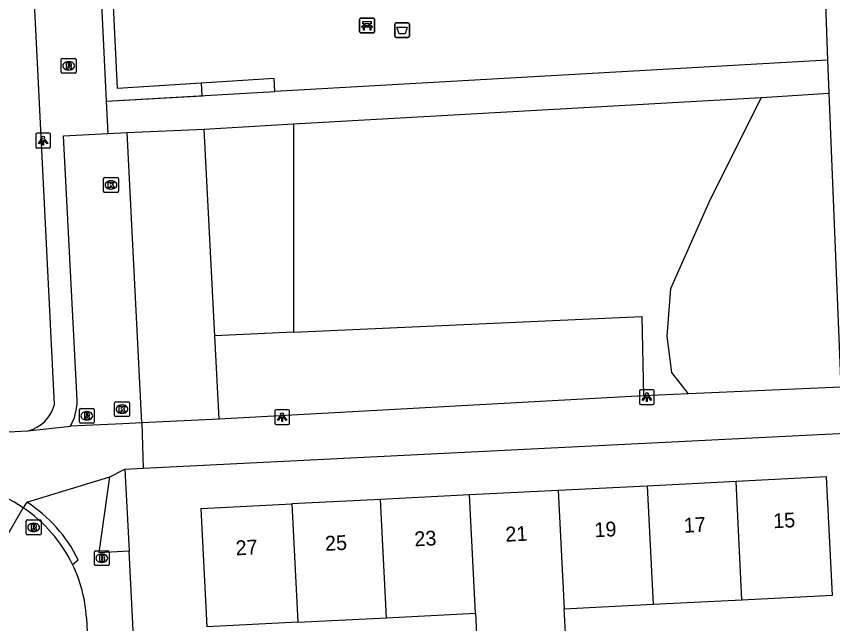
# Model space of a CAD drawing. Extents: x 161084 to 161928, y 385355 to 386522.
# Drawn here: x 161405.9 to 161461, y 386008.9 to 386049.9 of the extents above; entities that cross this region are included whole.
import ezdxf

# ---------------------------------------------------------------- set-up
doc = ezdxf.new("R2010")
doc.units = 0
for name, color, linetype in [('IMGEO_Afvalbak', 7, 'Continuous'), ('IMGEO_Bank', 7, 'Continuous'), ('IMGEO_Brandkraan', 7, 'Continuous'), ('IMGEO_Groenvoorziening', 7, 'Continuous'), ('IMGEO_Haag', 7, 'Continuous'), ('IMGEO_Kolk', 7, 'Continuous'), ('IMGEO_Lichtpunt', 7, 'Continuous'), ('IMGEO_Pand', 7, 'Continuous'), ('IMGEO_Pand_nummerreeks', 7, 'Continuous'), ('IMGEO_Parkeervlak_open', 7, 'Continuous'), ('IMGEO_Rijbaan_lokaal_open', 7, 'Continuous'), ('IMGEO_Rioolput', 7, 'Continuous'), ('IMGEO_Voetpad_halfverhard', 7, 'Continuous'), ('IMGEO_Voetpad_open', 7, 'Continuous')]:
    doc.layers.add(name, color=color, linetype=linetype)

msp = doc.modelspace()

# ---------------------------------------------------------------- linework, layer by layer
at = {"layer": 'IMGEO_Afvalbak'}
for p, q in [((161431.433, 386048.571), (161431.433, 386049.371)), ((161431.433, 386049.371), (161431.433, 386048.571)), ((161431.533, 386049.471), (161432.323, 386049.471)), ((161432.323, 386049.471), (161431.533, 386049.471)), ((161432.423, 386049.371), (161432.423, 386048.571)), ((161432.423, 386048.571), (161432.423, 386049.371)), ((161432.323, 386048.471), (161431.533, 386048.471)), ((161431.533, 386048.471), (161432.323, 386048.471))]:
    msp.add_line(p, q, dxfattribs=at)
msp.add_lwpolyline([(161431.576, 386049.185), (161432.28, 386049.185), (161432.131, 386048.715), (161431.725, 386048.715), (161431.576, 386049.185)], dxfattribs=at)
for centre, start, end in [((161431.533, 386049.371), 90, 180), ((161431.533, 386049.371), 90, 180), ((161432.323, 386049.371), 0, 90), ((161432.323, 386049.371), 360, 90), ((161431.533, 386048.571), 180, 270), ((161431.533, 386048.571), 180, 270), ((161432.323, 386048.571), 270, 0), ((161432.323, 386048.571), 270, 0)]:
    msp.add_arc(centre, 0.1, start, end, dxfattribs=at)
at = {"layer": 'IMGEO_Bank'}
for p, q in [((161429.066, 386048.86), (161429.066, 386049.701)), ((161429.066, 386049.701), (161429.066, 386048.86)), ((161429.141, 386049.785), (161429.982, 386049.785)), ((161429.982, 386049.785), (161429.141, 386049.785)), ((161429.375, 386049.291), (161429.375, 386049.397)), ((161429.419, 386049.397), (161429.419, 386049.291)), ((161429.707, 386049.403), (161429.425, 386049.403)), ((161429.425, 386049.285), (161429.707, 386049.285)), ((161429.713, 386049.291), (161429.713, 386049.397)), ((161429.757, 386049.397), (161429.757, 386049.291)), ((161430.066, 386049.71), (161430.066, 386048.869)), ((161430.066, 386048.869), (161430.066, 386049.71)), ((161429.991, 386048.785), (161429.15, 386048.785)), ((161429.15, 386048.785), (161429.991, 386048.785)), ((161429.763, 386049.183), (161429.37, 386049.183))]:
    msp.add_line(p, q, dxfattribs=at)
for points in [[(161429.313, 386049.183), (161429.171, 386049.183), (161429.283, 386049.285), (161429.369, 386049.285)], [(161429.369, 386049.403), (161429.283, 386049.403), (161429.283, 386049.564), (161429.846, 386049.564), (161429.846, 386049.403), (161429.763, 386049.403)], [(161429.763, 386049.285), (161429.846, 386049.285), (161429.958, 386049.183), (161429.819, 386049.183)], [(161429.363, 386049.176), (161429.363, 386048.969), (161429.32, 386048.969), (161429.32, 386049.176)], [(161429.813, 386049.176), (161429.813, 386048.969), (161429.769, 386048.969), (161429.769, 386049.176)]]:
    msp.add_lwpolyline(points, dxfattribs=at)
for centre, radius, start, end in [((161429.144, 386049.707), 0.0779, 92.4484, 184.2845), ((161429.144, 386049.707), 0.0779, 92.4484, 184.2845), ((161429.368, 386049.396), 0.00671, 2.8957, 87.1043), ((161429.368, 386049.292), 0.00671, 272.8957, 357.1043), ((161429.425, 386049.396), 0.00671, 92.8957, 177.1043), ((161429.425, 386049.292), 0.00671, 182.8957, 267.1043), ((161429.707, 386049.396), 0.00671, 2.8957, 87.1043), ((161429.707, 386049.292), 0.00671, 272.8957, 357.1043), ((161429.764, 386049.396), 0.00671, 92.8957, 177.1043), ((161429.764, 386049.292), 0.00671, 182.8957, 267.1043), ((161429.988, 386049.707), 0.0779, 2.4484, 94.2845), ((161429.988, 386049.707), 0.0779, 2.4484, 94.2845), ((161429.144, 386048.863), 0.0779, 182.4484, 274.2845), ((161429.144, 386048.863), 0.0779, 182.4484, 274.2845), ((161429.313, 386049.176), 0.00671, 2.8957, 87.1043), ((161429.37, 386049.176), 0.00671, 92.8957, 177.1043), ((161429.762, 386049.176), 0.00671, 2.8957, 87.1043), ((161429.819, 386049.176), 0.00671, 92.8957, 177.1043), ((161429.988, 386048.863), 0.0779, 272.4484, 4.2845), ((161429.988, 386048.863), 0.0779, 272.4484, 4.2845)]:
    msp.add_arc(centre, radius, start, end, dxfattribs=at)
at = {"layer": 'IMGEO_Brandkraan'}
for p, q in [((161411.168, 386012.895), (161411.168, 386013.747)), ((161411.243, 386013.821), (161412.095, 386013.821)), ((161411.656, 386013.601), (161411.681, 386013.601)), ((161412.169, 386013.747), (161412.169, 386012.895)), ((161411.679, 386013.041), (161411.654, 386013.041)), ((161412.095, 386012.821), (161411.243, 386012.821))]:
    msp.add_line(p, q, dxfattribs=at)
for points in [[(161411.168, 386012.895), (161411.168, 386013.747)], [(161411.243, 386013.821), (161412.095, 386013.821)], [(161411.516, 386013.521), (161411.516, 386013.121), (161411.729, 386013.121)], [(161411.747, 386013.521), (161411.516, 386013.521)], [(161412.169, 386013.747), (161412.169, 386012.895)], [(161411.695, 386013.44), (161411.641, 386013.44), (161411.641, 386013.364)], [(161411.641, 386013.364), (161411.694, 386013.364)], [(161411.703, 386013.288), (161411.641, 386013.288), (161411.641, 386013.207)], [(161411.641, 386013.207), (161411.703, 386013.207)], [(161412.095, 386012.821), (161411.243, 386012.821)]]:
    msp.add_lwpolyline(points, dxfattribs=at)
for centre, radius, start, end in [((161411.245, 386013.745), 0.0765, 91.552, 178.448), ((161411.245, 386013.745), 0.0765, 91.552, 178.448), ((161411.751, 386013.376), 0.145, 59.4692, 91.5367), ((161411.776, 386013.423), 0.0922, 285.5137, 58.1501), ((161412.093, 386013.745), 0.0765, 1.552, 88.448), ((161412.093, 386013.745), 0.0765, 1.552, 88.448), ((161411.696, 386013.402), 0.0379, 267.8285, 90.9355), ((161411.704, 386013.247), 0.0404, 269.8759, 90.5077), ((161411.735, 386013.372), 0.251, 268.6676, 293.5347), ((161411.781, 386013.231), 0.105, 301.3115, 78.989), ((161411.245, 386012.897), 0.0765, 181.552, 268.448), ((161411.245, 386012.897), 0.0765, 181.552, 268.448), ((161412.093, 386012.897), 0.0765, 271.552, 358.448), ((161412.093, 386012.897), 0.0765, 271.552, 358.448)]:
    msp.add_arc(centre, radius, start, end, dxfattribs=at)
for centre, major_axis, ratio, start_param, end_param in [((161411.655, 386013.321), (-0.387, 0.002), 0.722429, 4.712389, 7.853982), ((161411.68, 386013.321), (-0.39, 0.002), 0.717154, 1.570796, 4.712389)]:
    msp.add_ellipse(centre, major_axis=major_axis, ratio=ratio, start_param=start_param, end_param=end_param, dxfattribs=at)
at = {"layer": 'IMGEO_Groenvoorziening'}
for points in [[(161423.341, 386044.82), (161423.29, 386045.714), (161412.729, 386045.023)], [(161451.258, 386024.424), (161450.127, 386025.863), (161449.813, 386028.308), (161450.06, 386031.537), (161452.727, 386037.57), (161456.179, 386044.432)], [(161424.609, 386042.638), (161424.609, 386028.58)], [(161424.609, 386028.58), (161448.104, 386029.642), (161448.227, 386024.292)], [(161424.609, 386028.58), (161419.289, 386028.34)]]:
    msp.add_lwpolyline(points, dxfattribs=at)
at = {"layer": 'IMGEO_Haag'}
for points in [[(161412.729, 386045.023), (161411.827, 386063.66), (161411.99, 386074.551), (161413.442, 386096.342), (161413.521, 386097.88), (161419.758, 386097.471), (161419.807, 386098.189), (161412.791, 386098.649)], [(161411.969, 386044.171), (161418.447, 386044.541), (161418.4, 386045.394), (161412.729, 386045.023)]]:
    msp.add_lwpolyline(points, dxfattribs=at)
at = {"layer": 'IMGEO_Kolk'}
for p, q in [((161411.785, 386038.095), (161411.785, 386038.947)), ((161411.86, 386039.021), (161412.712, 386039.021)), ((161412.273, 386038.801), (161412.298, 386038.801)), ((161412.786, 386038.947), (161412.786, 386038.095)), ((161412.296, 386038.241), (161412.271, 386038.241)), ((161412.712, 386038.021), (161411.86, 386038.021)), ((161412.53, 386022.963), (161412.53, 386023.815)), ((161412.605, 386023.889), (161413.457, 386023.889)), ((161413.018, 386023.669), (161413.043, 386023.669)), ((161413.531, 386023.815), (161413.531, 386022.963)), ((161413.457, 386022.889), (161412.605, 386022.889)), ((161413.041, 386023.109), (161413.016, 386023.109))]:
    msp.add_line(p, q, dxfattribs=at)
for points in [[(161411.785, 386038.095), (161411.785, 386038.947)], [(161411.86, 386039.021), (161412.712, 386039.021)], [(161412.786, 386038.947), (161412.786, 386038.095)], [(161412.106, 386038.721), (161412.229, 386038.721), (161412.229, 386038.57), (161412.359, 386038.721), (161412.523, 386038.721), (161412.377, 386038.57), (161412.53, 386038.321), (161412.378, 386038.321), (161412.293, 386038.485), (161412.229, 386038.418), (161412.229, 386038.321), (161412.106, 386038.321), (161412.106, 386038.721)], [(161412.712, 386038.021), (161411.86, 386038.021)], [(161412.53, 386022.963), (161412.53, 386023.815)], [(161412.605, 386023.889), (161413.457, 386023.889)], [(161412.851, 386023.589), (161412.974, 386023.589), (161412.974, 386023.438), (161413.104, 386023.589), (161413.268, 386023.589), (161413.122, 386023.438), (161413.275, 386023.189), (161413.123, 386023.189), (161413.038, 386023.353), (161412.974, 386023.286), (161412.974, 386023.189), (161412.851, 386023.189), (161412.851, 386023.589)], [(161413.531, 386023.815), (161413.531, 386022.963)], [(161413.457, 386022.889), (161412.605, 386022.889)]]:
    msp.add_lwpolyline(points, dxfattribs=at)
for centre, start, end in [((161411.862, 386038.945), 91.552, 178.448), ((161411.862, 386038.945), 91.552, 178.448), ((161412.71, 386038.945), 1.552, 88.448), ((161412.71, 386038.945), 1.552, 88.448), ((161411.862, 386038.097), 181.552, 268.448), ((161411.862, 386038.097), 181.552, 268.448), ((161412.71, 386038.097), 271.552, 358.448), ((161412.71, 386038.097), 271.552, 358.448), ((161412.607, 386023.813), 91.552, 178.448), ((161412.607, 386023.813), 91.552, 178.448), ((161413.455, 386023.813), 1.552, 88.448), ((161413.455, 386023.813), 1.552, 88.448), ((161412.607, 386022.965), 181.552, 268.448), ((161412.607, 386022.965), 181.552, 268.448), ((161413.455, 386022.965), 271.552, 358.448), ((161413.455, 386022.965), 271.552, 358.448)]:
    msp.add_arc(centre, 0.0765, start, end, dxfattribs=at)
for centre, major_axis, ratio, start_param, end_param in [((161412.272, 386038.521), (-0.387, 0.002), 0.722429, 4.712389, 7.853982), ((161412.297, 386038.521), (-0.39, 0.002), 0.717154, 1.570796, 4.712389), ((161413.017, 386023.389), (-0.387, 0.002), 0.722429, 4.712389, 7.853982), ((161413.042, 386023.389), (-0.39, 0.002), 0.717154, 1.570796, 4.712389)]:
    msp.add_ellipse(centre, major_axis=major_axis, ratio=ratio, start_param=start_param, end_param=end_param, dxfattribs=at)
at = {"layer": 'IMGEO_Lichtpunt'}
for p, q in [((161407.211, 386041.918), (161407.211, 386041.111)), ((161407.211, 386041.918), (161407.211, 386041.111)), ((161408.113, 386042.013), (161407.305, 386042.013)), ((161408.113, 386042.013), (161407.305, 386042.013)), ((161408.207, 386041.111), (161408.207, 386041.918)), ((161408.207, 386041.111), (161408.207, 386041.918)), ((161407.305, 386041.017), (161408.113, 386041.017)), ((161407.305, 386041.017), (161408.113, 386041.017)), ((161447.945, 386024.604), (161447.945, 386023.797)), ((161447.945, 386024.604), (161447.945, 386023.797)), ((161448.847, 386024.699), (161448.039, 386024.699)), ((161448.847, 386024.699), (161448.039, 386024.699)), ((161448.941, 386023.797), (161448.941, 386024.604)), ((161448.941, 386023.797), (161448.941, 386024.604)), ((161448.039, 386023.703), (161448.847, 386023.703)), ((161448.039, 386023.703), (161448.847, 386023.703)), ((161423.335, 386023.251), (161423.335, 386022.444)), ((161423.335, 386023.251), (161423.335, 386022.444)), ((161424.237, 386023.346), (161423.429, 386023.346)), ((161424.237, 386023.346), (161423.429, 386023.346)), ((161424.331, 386022.444), (161424.331, 386023.251)), ((161424.331, 386022.444), (161424.331, 386023.251)), ((161423.429, 386022.35), (161424.237, 386022.35)), ((161423.429, 386022.35), (161424.237, 386022.35))]:
    msp.add_line(p, q, dxfattribs=at)
for points in [[(161407.585, 386041.582), (161407.624, 386041.554), (161407.436, 386041.292), (161407.398, 386041.319), (161407.585, 386041.582)], [(161407.797, 386041.554), (161407.835, 386041.581), (161408.022, 386041.319), (161407.983, 386041.291), (161407.797, 386041.554)], [(161407.687, 386041.534), (161407.734, 386041.534), (161407.734, 386041.212), (161407.687, 386041.212), (161407.687, 386041.534)], [(161448.319, 386024.268), (161448.358, 386024.24), (161448.17, 386023.978), (161448.132, 386024.005), (161448.319, 386024.268)], [(161448.421, 386024.22), (161448.468, 386024.22), (161448.468, 386023.898), (161448.421, 386023.898), (161448.421, 386024.22)], [(161448.531, 386024.24), (161448.569, 386024.267), (161448.756, 386024.005), (161448.717, 386023.977), (161448.531, 386024.24)], [(161423.709, 386022.915), (161423.748, 386022.887), (161423.56, 386022.625), (161423.522, 386022.652), (161423.709, 386022.915)], [(161423.811, 386022.867), (161423.858, 386022.867), (161423.858, 386022.545), (161423.811, 386022.545), (161423.811, 386022.867)], [(161423.921, 386022.887), (161423.959, 386022.914), (161424.146, 386022.652), (161424.107, 386022.624), (161423.921, 386022.887)]]:
    msp.add_lwpolyline(points, dxfattribs=at)
for centre in [(161407.71, 386041.716), (161448.444, 386024.402), (161423.834, 386023.049)]:
    msp.add_circle(centre, 0.0994, dxfattribs=at)
for centre, start, end in [((161407.305, 386041.918), 90, 180), ((161407.305, 386041.918), 90, 180), ((161408.113, 386041.918), 0, 90), ((161408.113, 386041.918), 0, 90), ((161407.305, 386041.111), 180, 270), ((161407.305, 386041.111), 180, 270), ((161408.113, 386041.111), 270, 0), ((161408.113, 386041.111), 270, 360), ((161448.039, 386024.604), 90, 180), ((161448.039, 386024.604), 90, 180), ((161448.847, 386024.604), 0, 90), ((161448.847, 386024.604), 0, 90), ((161448.039, 386023.797), 180, 270), ((161448.039, 386023.797), 180, 270), ((161448.847, 386023.797), 270, 0), ((161448.847, 386023.797), 270, 360), ((161423.429, 386023.251), 90, 180), ((161423.429, 386023.251), 90, 180), ((161424.237, 386023.251), 0, 90), ((161424.237, 386023.251), 0, 90), ((161423.429, 386022.444), 180, 270), ((161423.429, 386022.444), 180, 270), ((161424.237, 386022.444), 270, 0), ((161424.237, 386022.444), 270, 360)]:
    msp.add_arc(centre, 0.0946, start, end, dxfattribs=at)
at = {"layer": 'IMGEO_Pand'}
for points in [[(161454.459, 386018.5), (161448.464, 386018.197)], [(161454.862, 386010.515), (161460.976, 386010.824), (161460.573, 386018.809), (161454.459, 386018.5)], [(161454.862, 386010.515), (161454.459, 386018.5)], [(161442.468, 386017.894), (161436.472, 386017.592)], [(161448.464, 386018.197), (161442.468, 386017.894)], [(161442.468, 386017.894), (161442.871, 386009.909)], [(161448.464, 386018.197), (161448.867, 386010.212)], [(161436.472, 386017.592), (161430.477, 386017.289)], [(161436.876, 386009.607), (161436.472, 386017.592)], [(161424.884, 386009.001), (161418.771, 386008.692), (161418.367, 386016.677), (161424.481, 386016.986)], [(161430.477, 386017.289), (161424.481, 386016.986)], [(161424.481, 386016.986), (161424.884, 386009.001)], [(161430.88, 386009.304), (161430.477, 386017.289)], [(161442.871, 386009.909), (161448.867, 386010.212)], [(161448.867, 386010.212), (161454.862, 386010.515)], [(161430.88, 386009.304), (161436.876, 386009.607)], [(161436.876, 386009.607), (161437.019, 386006.766), (161443.014, 386007.068), (161442.871, 386009.909)], [(161424.884, 386009.001), (161430.88, 386009.304)]]:
    msp.add_lwpolyline(points, dxfattribs=at)
at = {"layer": 'IMGEO_Parkeervlak_open'}
for points in [[(161419.289, 386028.34), (161418.571, 386042.289)], [(161419.578, 386022.714), (161419.289, 386028.34)]]:
    msp.add_lwpolyline(points, dxfattribs=at)
at = {"layer": 'IMGEO_Rijbaan_lokaal_open'}
for points in [[(161409.558, 386022.237), (161409.7, 386022.521), (161409.816, 386022.818), (161409.904, 386023.123), (161409.966, 386023.435), (161409.999, 386023.751), (161410.005, 386023.991), (161409.089, 386041.831), (161412.082, 386042.002)], [(161412.082, 386042.002), (161413.383, 386042.06)], [(161414.372, 386022.466), (161413.383, 386042.06)], [(161414.372, 386022.466), (161413.099, 386022.405), (161409.558, 386022.237)], [(161402.186, 386009.476), (161406.357, 386016.734)], [(161410.629, 386009.305), (161411.335, 385994.667), (161413.296, 385956.735), (161413.505, 385952.859), (161414.906, 385925.074)]]:
    msp.add_lwpolyline(points, dxfattribs=at)
for centre, radius, start, end in [((161400.859, 386008.614), 9.806, 55.8997, 73.1485), ((161400.848, 386008.564), 9.854, 26.0357, 56.0083), ((161401.317, 386008.808), 9.325, 3.0532, 25.9502)]:
    msp.add_arc(centre, radius, start, end, dxfattribs=at)
at = {"layer": 'IMGEO_Rioolput'}
for p, q in [((161409.012, 386047.062), (161409.864, 386047.062)), ((161408.937, 386046.136), (161408.937, 386046.988)), ((161409.425, 386046.842), (161409.45, 386046.842)), ((161409.938, 386046.988), (161409.938, 386046.136)), ((161409.864, 386046.062), (161409.012, 386046.062)), ((161409.448, 386046.282), (161409.423, 386046.282)), ((161410.231, 386023.438), (161411.083, 386023.438)), ((161410.156, 386022.512), (161410.156, 386023.364)), ((161410.644, 386023.218), (161410.669, 386023.218)), ((161411.157, 386023.364), (161411.157, 386022.512)), ((161411.083, 386022.438), (161410.231, 386022.438)), ((161410.667, 386022.658), (161410.642, 386022.658)), ((161406.572, 386014.977), (161406.572, 386015.829)), ((161406.647, 386015.903), (161407.499, 386015.903)), ((161407.06, 386015.683), (161407.085, 386015.683)), ((161407.573, 386015.829), (161407.573, 386014.977)), ((161407.083, 386015.123), (161407.058, 386015.123)), ((161407.499, 386014.903), (161406.647, 386014.903))]:
    msp.add_line(p, q, dxfattribs=at)
for points in [[(161409.012, 386047.062), (161409.864, 386047.062)], [(161408.937, 386046.136), (161408.937, 386046.988)], [(161409.526, 386046.76), (161409.274, 386046.762), (161409.274, 386046.362)], [(161409.274, 386046.362), (161409.398, 386046.362), (161409.398, 386046.524), (161409.409, 386046.524)], [(161409.452, 386046.681), (161409.398, 386046.681), (161409.398, 386046.6)], [(161409.398, 386046.6), (161409.45, 386046.6)], [(161409.938, 386046.988), (161409.938, 386046.136)], [(161409.864, 386046.062), (161409.012, 386046.062)], [(161409.456, 386046.495), (161409.527, 386046.362), (161409.667, 386046.362), (161409.602, 386046.488)], [(161410.231, 386023.438), (161411.083, 386023.438)], [(161410.156, 386022.512), (161410.156, 386023.364)], [(161410.745, 386023.136), (161410.493, 386023.138), (161410.493, 386022.738)], [(161410.493, 386022.738), (161410.617, 386022.738), (161410.617, 386022.9), (161410.628, 386022.9)], [(161410.671, 386023.057), (161410.617, 386023.057), (161410.617, 386022.976)], [(161410.617, 386022.976), (161410.669, 386022.976)], [(161410.675, 386022.871), (161410.746, 386022.738), (161410.886, 386022.738), (161410.821, 386022.864)], [(161411.157, 386023.364), (161411.157, 386022.512)], [(161411.083, 386022.438), (161410.231, 386022.438)], [(161406.572, 386014.977), (161406.572, 386015.829)], [(161406.647, 386015.903), (161407.499, 386015.903)], [(161407.573, 386015.829), (161407.573, 386014.977)], [(161407.161, 386015.601), (161406.909, 386015.603), (161406.909, 386015.203)], [(161406.909, 386015.203), (161407.033, 386015.203), (161407.033, 386015.365), (161407.044, 386015.365)], [(161407.087, 386015.522), (161407.033, 386015.522), (161407.033, 386015.441)], [(161407.033, 386015.441), (161407.085, 386015.441)], [(161407.091, 386015.336), (161407.162, 386015.203), (161407.302, 386015.203), (161407.237, 386015.329)], [(161407.499, 386014.903), (161406.647, 386014.903)]]:
    msp.add_lwpolyline(points, dxfattribs=at)
for centre, radius, start, end in [((161409.014, 386046.986), 0.0765, 91.552, 178.448), ((161409.014, 386046.986), 0.0765, 91.552, 178.448), ((161409.862, 386046.986), 0.0765, 1.552, 88.448), ((161409.862, 386046.986), 0.0765, 1.552, 88.448), ((161409.408, 386046.471), 0.0533, 26.0293, 88.6989), ((161409.434, 386046.789), 0.19, 274.7715, 282.9687), ((161409.458, 386046.585), 0.0964, 77.0061, 93.1865), ((161409.472, 386046.642), 0.0378, 276.6634, 79.6772), ((161409.525, 386046.65), 0.109, 350.3612, 89.416), ((161409.523, 386046.65), 0.112, 277.5842, 350.9817), ((161409.507, 386046.435), 0.108, 29.5134, 73.7905), ((161409.014, 386046.138), 0.0765, 181.552, 268.448), ((161409.014, 386046.138), 0.0765, 181.552, 268.448), ((161409.862, 386046.138), 0.0765, 271.552, 358.448), ((161409.862, 386046.138), 0.0765, 271.552, 358.448), ((161410.233, 386023.362), 0.0765, 91.552, 178.448), ((161410.233, 386023.362), 0.0765, 91.552, 178.448), ((161411.081, 386023.362), 0.0765, 1.552, 88.448), ((161411.081, 386023.362), 0.0765, 1.552, 88.448), ((161410.627, 386022.847), 0.0533, 26.0293, 88.6989), ((161410.653, 386023.165), 0.19, 274.7715, 282.9687), ((161410.677, 386022.961), 0.0964, 77.0061, 93.1865), ((161410.691, 386023.018), 0.0378, 276.6634, 79.6772), ((161410.744, 386023.026), 0.109, 350.3612, 89.416), ((161410.742, 386023.026), 0.112, 277.5842, 350.9817), ((161410.726, 386022.811), 0.108, 29.5134, 73.7905), ((161410.233, 386022.514), 0.0765, 181.552, 268.448), ((161410.233, 386022.514), 0.0765, 181.552, 268.448), ((161411.081, 386022.514), 0.0765, 271.552, 358.448), ((161411.081, 386022.514), 0.0765, 271.552, 358.448), ((161406.649, 386015.827), 0.0765, 91.552, 178.448), ((161406.649, 386015.827), 0.0765, 91.552, 178.448), ((161407.497, 386015.827), 0.0765, 1.552, 88.448), ((161407.497, 386015.827), 0.0765, 1.552, 88.448), ((161407.043, 386015.312), 0.0533, 26.0293, 88.6989), ((161407.069, 386015.63), 0.19, 274.7715, 282.9687), ((161407.093, 386015.426), 0.0964, 77.0061, 93.1865), ((161407.107, 386015.483), 0.0378, 276.6634, 79.6772), ((161407.16, 386015.491), 0.109, 350.3612, 89.416), ((161407.158, 386015.491), 0.112, 277.5842, 350.9817), ((161407.142, 386015.276), 0.108, 29.5134, 73.7905), ((161406.649, 386014.979), 0.0765, 181.552, 268.448), ((161406.649, 386014.979), 0.0765, 181.552, 268.448), ((161407.497, 386014.979), 0.0765, 271.552, 358.448), ((161407.497, 386014.979), 0.0765, 271.552, 358.448)]:
    msp.add_arc(centre, radius, start, end, dxfattribs=at)
for centre, major_axis, ratio, start_param, end_param in [((161409.424, 386046.562), (-0.387, 0.002), 0.722429, 4.712389, 7.853982), ((161409.449, 386046.562), (-0.39, 0.002), 0.717154, 1.570796, 4.712389), ((161410.643, 386022.938), (-0.387, 0.002), 0.722429, 4.712389, 7.853982), ((161410.668, 386022.938), (-0.39, 0.002), 0.717154, 1.570796, 4.712389), ((161407.059, 386015.403), (-0.387, 0.002), 0.722429, 4.712389, 7.853982), ((161407.084, 386015.403), (-0.39, 0.002), 0.717154, 1.570796, 4.712389)]:
    msp.add_ellipse(centre, major_axis=major_axis, ratio=ratio, start_param=start_param, end_param=end_param, dxfattribs=at)
at = {"layer": 'IMGEO_Voetpad_halfverhard'}
for points in [[(161459.051, 386091.279), (161460.642, 386046.95)], [(161460.642, 386046.95), (161423.341, 386044.82)], [(161460.642, 386046.95), (161460.731, 386044.726)], [(161411.969, 386044.171), (161423.341, 386044.82)], [(161424.609, 386042.638), (161456.179, 386044.432)], [(161456.179, 386044.432), (161460.731, 386044.726)], [(161460.731, 386044.726), (161461.522, 386024.865)], [(161413.383, 386042.06), (161418.571, 386042.289)], [(161418.571, 386042.289), (161424.609, 386042.638)]]:
    msp.add_lwpolyline(points, dxfattribs=at)
at = {"layer": 'IMGEO_Voetpad_open'}
for points in [[(161411.081, 386062.487), (161411.969, 386044.171)], [(161408.477, 386023.702), (161406.633, 386060.792)], [(161411.969, 386044.171), (161412.082, 386042.002)], [(161461.522, 386024.865), (161452.284, 386024.469), (161451.258, 386024.424)], [(161448.227, 386024.292), (161419.578, 386022.714)], [(161451.258, 386024.424), (161448.227, 386024.292)], [(161419.578, 386022.714), (161414.372, 386022.466)], [(161414.372, 386022.466), (161414.464, 386019.403)], [(161375.581, 386020.367), (161380.148, 386020.594), (161394.231, 386021.295), (161406.67, 386021.914)], [(161406.67, 386021.914), (161409.558, 386022.237)], [(161414.464, 386019.403), (161463.668, 386021.852)], [(161412.209, 386018.819), (161413.232, 386019.342)], [(161413.232, 386019.342), (161414.464, 386019.403)], [(161413.232, 386019.342), (161413.518, 386013.79)], [(161406.62, 386017.115), (161412.209, 386018.819)], [(161413.518, 386013.79), (161411.502, 386013.687), (161412.209, 386018.819)], [(161406.62, 386017.115), (161406.357, 386016.734)], [(161414.399, 385996.543), (161414.222, 386000), (161413.518, 386013.79)], [(161409.702, 386012.889), (161410.079, 386013.217)]]:
    msp.add_lwpolyline(points, dxfattribs=at)
for centre, radius, start, end in [((161406.054, 386024.344), 2.507, 284.2301, 345.1642), ((161401.145, 386008.773), 9.979, 26.4482, 56.7221)]:
    msp.add_arc(centre, radius, start, end, dxfattribs=at)

# ---------------------------------------------------------------- texts
at = {"layer": 'IMGEO_Pand_nummerreeks'}
for s, rotation, p in [('15', 2.8918, (161456.99, 386015.343)), ('19', 2.8918, (161444.931, 386014.734)), ('17', 2.8918, (161450.96, 386015.039)), ('23', 2.8918, (161432.781, 386014.121)), ('21', 2.8934, (161438.923, 386014.432)), ('27', 2.8918, (161420.722, 386013.512)), ('25', 2.8918, (161426.751, 386013.817))]:
    msp.add_text(s, height=1, rotation=rotation, dxfattribs=at).set_placement(p)

doc.saveas('drawing.dxf')
